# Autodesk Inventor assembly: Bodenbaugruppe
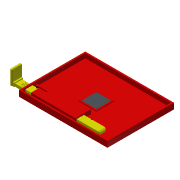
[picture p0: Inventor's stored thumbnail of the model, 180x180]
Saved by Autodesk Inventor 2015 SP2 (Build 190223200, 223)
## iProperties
Created: 2017-07
Part Number: Bodenbaugruppe
Document SubType Name: Assembly
Designer: UR
Author: UR
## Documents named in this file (5)
- X:\Tresor_SSD\Arbeit\Unterricht\Stoff\Inventor\Locher 05 Version 2\Boden-BG.iam
- X:\Tresor_SSD\Arbeit\Unterricht\Stoff\Inventor\Locher 05 Version 2\Bodenplatte.ipt
- X:\Tresor_SSD\Arbeit\Unterricht\Stoff\Inventor\Locher 05 Version 2\Anschlagschieber.ipt
- X:\Tresor_SSD\Arbeit\Unterricht\Stoff\Inventor\Locher 05 Version 2\Anschlagfuehrung.ipt
- X:\Tresor_SSD\Arbeit\Unterricht\Stoff\Inventor\Locher 05 Version 2\Magnetplatte.ipt
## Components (4 placed, 4 different names)
1. Bodenplatte:1 — Passend:15, Passend:16, Passend:17, Fluchtend:1, Passend:18, Fluchtend:2, Passend:19
2. Anschlagschieber:1 — Passend:19, Passend:20, Fluchtend:3
3. Anschlagfuehrung:1 — Fluchtend:1, Passend:18, Fluchtend:2, Passend:20, Fluchtend:3
4. Magnetplatte:1 — Passend:15, Passend:16, Passend:17
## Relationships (9: Mate 6, Flush 3)
- Passend:15 [Mate]: Bodenplatte:1 ↔ Magnetplatte:1
- Passend:16 [Mate]: Bodenplatte:1 ↔ Magnetplatte:1
- Passend:17 [Mate]: Bodenplatte:1 ↔ Magnetplatte:1
- Fluchtend:1 [Flush]: Bodenplatte:1 ↔ Anschlagfuehrung:1
- Passend:18 [Mate]: Bodenplatte:1 ↔ Anschlagfuehrung:1
- Fluchtend:2 [Flush]: Bodenplatte:1 ↔ Anschlagfuehrung:1
- Passend:19 [Mate]: Bodenplatte:1 ↔ Anschlagschieber:1
- Passend:20 [Mate]: Anschlagschieber:1 ↔ Anschlagfuehrung:1
- Fluchtend:3 [Flush]: Anschlagschieber:1 ↔ Anschlagfuehrung:1
